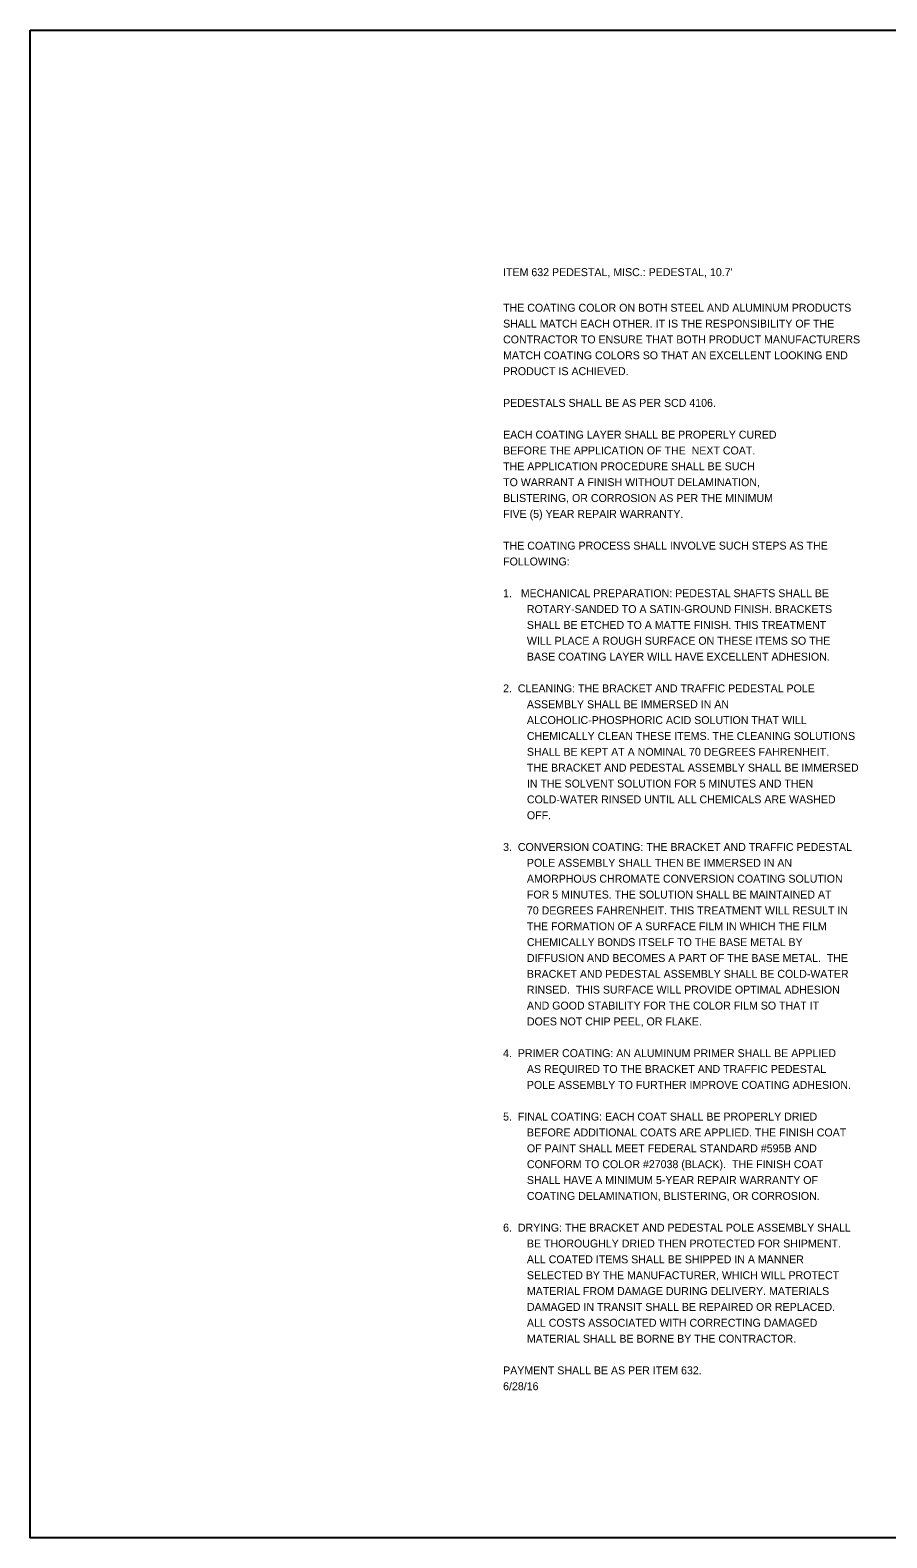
# Model space of a CAD drawing. Extents: x -50.5 to 43.5, y -13 to 19.8.
# Drawn here: x -50.54 to -35.41, y -10.34 to 16.28 of the extents above; entities that cross this region are included whole.
import ezdxf

# ---------------------------------------------------------------- set-up
doc = ezdxf.new("R2010")
doc.units = 0
doc.layers.add('SH_Data', color=7, linetype='Continuous')
doc.layers.add('SH_Text', color=7, linetype='Continuous')

msp = doc.modelspace()

# ---------------------------------------------------------------- linework, layer by layer
at = {"layer": 'SH_Text'}
msp.add_lwpolyline([(-50.537, 16.279), (-10.414, 16.279), (-10.414, -10.338), (-50.537, -10.338)], close=True, dxfattribs=at)

# ---------------------------------------------------------------- texts
at = {"layer": 'SH_Data'}
msp.add_text("ITEM 632 PEDESTAL, MISC.: PEDESTAL, 10.7'", height=0.14, rotation=360, dxfattribs=at).set_placement((-42.186, 11.937))
at = {"layer": 'SH_Text'}
for s, p in [('THE COATING COLOR ON BOTH STEEL AND ALUMINUM PRODUCTS ', (-42.186, 11.309)), ('SHALL MATCH EACH OTHER. IT IS THE RESPONSIBILITY OF THE ', (-42.186, 11.029)), ('CONTRACTOR TO ENSURE THAT BOTH PRODUCT MANUFACTURERS ', (-42.186, 10.749)), ('MATCH COATING COLORS SO THAT AN EXCELLENT LOOKING END ', (-42.186, 10.469)), ('PRODUCT IS ACHIEVED. ', (-42.186, 10.189)), ('PEDESTALS SHALL BE AS PER SCD 4106.  ', (-42.186, 9.629)), ('EACH COATING LAYER SHALL BE PROPERLY CURED', (-42.186, 9.069)), ('BEFORE THE APPLICATION OF THE  NEXT COAT.', (-42.186, 8.789)), ('THE APPLICATION PROCEDURE SHALL BE SUCH', (-42.186, 8.509)), ('TO WARRANT A FINISH WITHOUT DELAMINATION,', (-42.186, 8.229)), ('BLISTERING, OR CORROSION AS PER THE MINIMUM', (-42.186, 7.949)), ('FIVE (5) YEAR REPAIR WARRANTY. ', (-42.186, 7.669)), ('THE COATING PROCESS SHALL INVOLVE SUCH STEPS AS THE', (-42.186, 7.109)), ('FOLLOWING:', (-42.186, 6.829)), ('1.   MECHANICAL PREPARATION: PEDESTAL SHAFTS SHALL BE ', (-42.186, 6.269)), ('ROTARY-SANDED TO A SATIN-GROUND FINISH. BRACKETS ', (-41.766, 5.989)), ('SHALL BE ETCHED TO A MATTE FINISH. THIS TREATMENT ', (-41.766, 5.709)), ('WILL PLACE A ROUGH SURFACE ON THESE ITEMS SO THE ', (-41.766, 5.429)), ('BASE COATING LAYER WILL HAVE EXCELLENT ADHESION.', (-41.766, 5.149)), ('2.  CLEANING: THE BRACKET AND TRAFFIC PEDESTAL POLE ', (-42.186, 4.589)), ('ASSEMBLY SHALL BE IMMERSED IN AN ', (-41.766, 4.309)), ('ALCOHOLIC-PHOSPHORIC ACID SOLUTION THAT WILL ', (-41.766, 4.029)), ('CHEMICALLY CLEAN THESE ITEMS. THE CLEANING SOLUTIONS ', (-41.766, 3.749)), ('SHALL BE KEPT AT A NOMINAL 70 DEGREES FAHRENHEIT.  ', (-41.766, 3.469)), ('THE BRACKET AND PEDESTAL ASSEMBLY SHALL BE IMMERSED ', (-41.766, 3.189)), ('IN THE SOLVENT SOLUTION FOR 5 MINUTES AND THEN ', (-41.766, 2.909)), ('COLD-WATER RINSED UNTIL ALL CHEMICALS ARE WASHED ', (-41.766, 2.629)), ('OFF.', (-41.766, 2.349)), ('3.  CONVERSION COATING: THE BRACKET AND TRAFFIC PEDESTAL ', (-42.186, 1.789)), ('POLE ASSEMBLY SHALL THEN BE IMMERSED IN AN ', (-41.766, 1.509)), ('AMORPHOUS CHROMATE CONVERSION COATING SOLUTION ', (-41.766, 1.229)), ('FOR 5 MINUTES. THE SOLUTION SHALL BE MAINTAINED AT ', (-41.766, 0.949)), ('70 DEGREES FAHRENHEIT. THIS TREATMENT WILL RESULT IN ', (-41.766, 0.669)), ('THE FORMATION OF A SURFACE FILM IN WHICH THE FILM ', (-41.766, 0.389)), ('CHEMICALLY BONDS ITSELF TO THE BASE METAL BY ', (-41.766, 0.109)), ('DIFFUSION AND BECOMES A PART OF THE BASE METAL.  THE ', (-41.766, -0.171)), ('BRACKET AND PEDESTAL ASSEMBLY SHALL BE COLD-WATER ', (-41.766, -0.451)), ('RINSED.  THIS SURFACE WILL PROVIDE OPTIMAL ADHESION ', (-41.766, -0.731)), ('AND GOOD STABILITY FOR THE COLOR FILM SO THAT IT ', (-41.766, -1.011)), ('DOES NOT CHIP PEEL, OR FLAKE. ', (-41.766, -1.291)), ('4.  PRIMER COATING: AN ALUMINUM PRIMER SHALL BE APPLIED ', (-42.186, -1.851)), ('AS REQUIRED TO THE BRACKET AND TRAFFIC PEDESTAL ', (-41.766, -2.131)), ('POLE ASSEMBLY TO FURTHER IMPROVE COATING ADHESION.', (-41.766, -2.411)), ('5.  FINAL COATING: EACH COAT SHALL BE PROPERLY DRIED ', (-42.186, -2.971)), ('BEFORE ADDITIONAL COATS ARE APPLIED. THE FINISH COAT ', (-41.766, -3.251)), ('OF PAINT SHALL MEET FEDERAL STANDARD #595B AND ', (-41.766, -3.531)), ('CONFORM TO COLOR #27038 (BLACK).  THE FINISH COAT ', (-41.766, -3.811)), ('SHALL HAVE A MINIMUM 5-YEAR REPAIR WARRANTY OF ', (-41.766, -4.091)), ('COATING DELAMINATION, BLISTERING, OR CORROSION.', (-41.766, -4.371)), ('6.  DRYING: THE BRACKET AND PEDESTAL POLE ASSEMBLY SHALL ', (-42.186, -4.931)), ('BE THOROUGHLY DRIED THEN PROTECTED FOR SHIPMENT. ', (-41.766, -5.211)), ('ALL COATED ITEMS SHALL BE SHIPPED IN A MANNER ', (-41.766, -5.491)), ('SELECTED BY THE MANUFACTURER, WHICH WILL PROTECT ', (-41.766, -5.771)), ('MATERIAL FROM DAMAGE DURING DELIVERY. MATERIALS ', (-41.766, -6.051)), ('DAMAGED IN TRANSIT SHALL BE REPAIRED OR REPLACED.  ', (-41.766, -6.331)), ('ALL COSTS ASSOCIATED WITH CORRECTING DAMAGED ', (-41.766, -6.611)), ('MATERIAL SHALL BE BORNE BY THE CONTRACTOR.', (-41.766, -6.891)), ('PAYMENT SHALL BE AS PER ITEM 632.', (-42.186, -7.451)), ('6/28/16', (-42.186, -7.731))]:
    msp.add_text(s, height=0.14, rotation=360, dxfattribs=at).set_placement(p)

doc.saveas('drawing.dxf')
